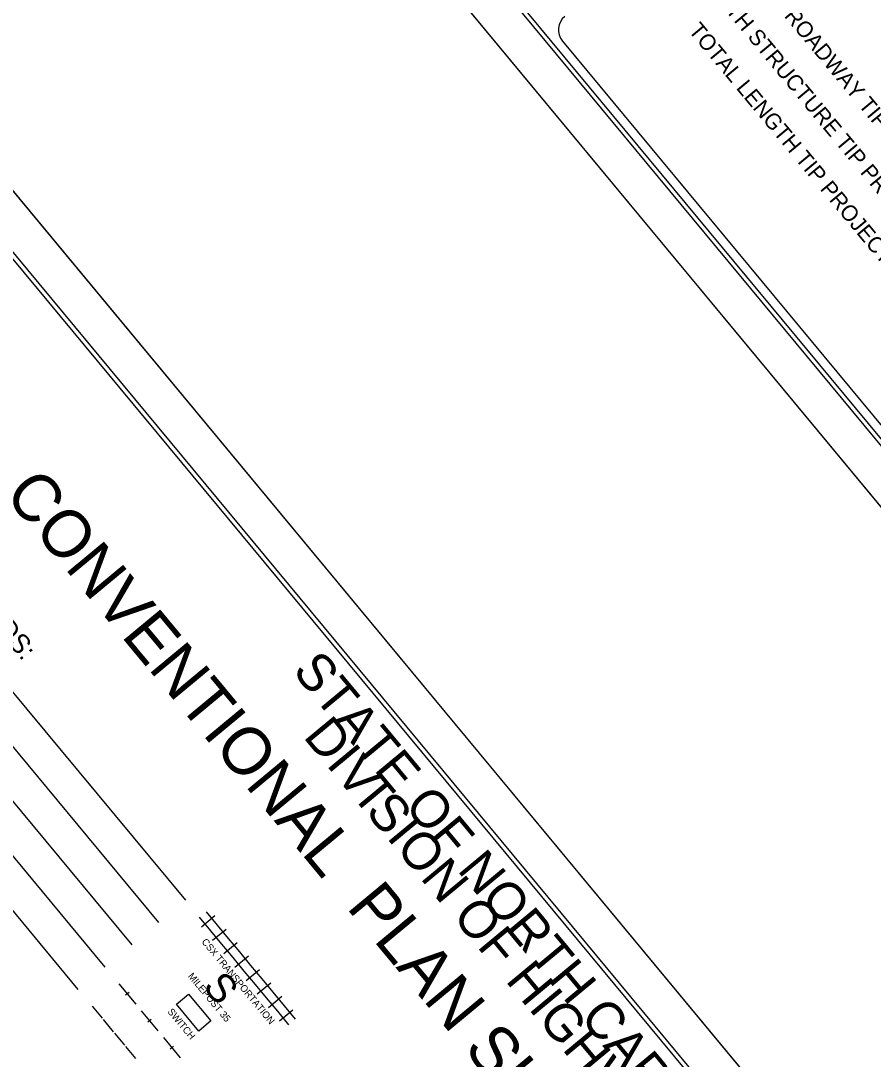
# Model space of a CAD drawing. Extents: x 2054826 to 2060231, y 685508 to 690809.
# Drawn here: x 2057466 to 2058198, y 687750 to 688643 of the extents above; entities that cross this region are included whole.
import ezdxf

# ---------------------------------------------------------------- set-up
doc = ezdxf.new("R2010")
doc.units = 0
for name, color, linetype in [('Old_Level_11', 7, 'Continuous'), ('Sheet Cutting Line CELL', 7, 'Continuous'), ('Sheet Plot Border Inside CELL', 7, 'Continuous'), ('Sheet Plot Border Outside CELL', 7, 'Continuous'), ('Sheet Symbology CELL', 7, 'Continuous'), ('Sheet Title CELL', 7, 'Continuous')]:
    doc.layers.add(name, color=color, linetype=linetype)

msp = doc.modelspace()

# ---------------------------------------------------------------- linework, layer by layer
at = {"layer": 'Sheet Cutting Line CELL'}
for p, q in [((2057348.74, 689256.87), (2058961.15, 687312.44)), ((2058650.7, 687059.77), (2057038.28, 689004.2))]:
    msp.add_line(p, q, dxfattribs=at)
at = {"layer": 'Sheet Plot Border Inside CELL'}
for points in [[(2057387.09, 689263.34), (2058982.75, 687339.12), (2060201.02, 688349.37), (2058605.36, 690273.59)], [(2055806.54, 687957.44), (2057402.2, 686033.22), (2058620.47, 687043.47), (2057024.81, 688967.69)]]:
    msp.add_lwpolyline(points, close=True, dxfattribs=at)
at = {"layer": 'Sheet Plot Border Outside CELL'}
for points in [[(2060231.25, 688365.67), (2058618.84, 690310.09), (2057348.74, 689256.87), (2058961.15, 687312.44)], [(2055768.17, 687950.96), (2057380.59, 686006.53), (2058650.7, 687059.77), (2057038.28, 689004.2)]]:
    msp.add_lwpolyline(points, close=True, dxfattribs=at)
at = {"layer": 'Sheet Symbology CELL'}
for p, q in [((2057561.4, 687848.66), (2057355.62, 688096.81)), ((2057607.59, 687886.96), (2057455.91, 688069.87)), ((2057584.49, 687867.81), (2057441.3, 688040.49)), ((2057538.31, 687829.51), (2057379.21, 688021.37)), ((2057515.21, 687810.36), (2057356.12, 688002.22)), ((2057515.21, 687810.36), (2057356.12, 688002.22)), ((2057624.95, 687877.21), (2057634.53, 687865.67)), ((2057619.18, 687872.43), (2057628.75, 687860.88)), ((2057621.08, 687864.26), (2057632.63, 687873.83)), ((2057634.53, 687865.67), (2057644.1, 687854.12)), ((2057628.75, 687860.88), (2057638.33, 687849.33)), ((2057630.65, 687852.71), (2057642.2, 687862.29)), ((2057638.33, 687849.33), (2057647.9, 687837.79)), ((2057640.23, 687841.17), (2057651.78, 687850.74)), ((2057644.1, 687854.12), (2057653.68, 687842.57)), ((2057649.8, 687829.62), (2057661.35, 687839.19)), ((2057653.68, 687842.57), (2057663.25, 687831.03)), ((2057647.9, 687837.79), (2057657.48, 687826.24)), ((2057663.25, 687831.03), (2057672.83, 687819.48)), ((2057657.48, 687826.24), (2057667.05, 687814.69)), ((2057659.38, 687818.07), (2057670.93, 687827.65)), ((2057550.17, 687815.2), (2057564.54, 687797.88)), ((2057667.05, 687814.69), (2057676.63, 687803.15)), ((2057668.95, 687806.53), (2057680.5, 687816.1)), ((2057672.83, 687819.48), (2057682.4, 687807.93)), ((2057558.8, 687807.74), (2057555.91, 687805.35)), ((2057676.63, 687803.15), (2057686.2, 687791.6)), ((2057678.53, 687794.98), (2057690.08, 687804.55)), ((2057682.4, 687807.93), (2057691.98, 687796.39)), ((2057527.08, 687796.05), (2057535.7, 687785.66)), ((2057691.98, 687796.39), (2057701.55, 687784.84)), ((2057569.32, 687792.11), (2057583.69, 687774.79)), ((2057686.2, 687791.6), (2057695.78, 687780.05)), ((2057688.1, 687783.43), (2057699.65, 687793.01)), ((2057536.66, 687784.51), (2057545.27, 687774.12)), ((2057577.95, 687784.65), (2057575.06, 687782.25)), ((2057546.23, 687772.96), (2057554.85, 687762.57)), ((2057588.47, 687769.02), (2057602.84, 687751.7)), ((2057555.81, 687761.41), (2057564.42, 687751.02)), ((2057597.1, 687761.55), (2057594.21, 687759.16))]:
    msp.add_line(p, q, dxfattribs=at)
for points in [[(2058605.56, 687055.46), (2057169.32, 688787.43), (2055958.11, 687783.04), (2057394.35, 686051.07)], [(2057610.03, 687806.38), (2057629.18, 687783.29), (2057618.67, 687774.57), (2057599.52, 687797.67)]]:
    msp.add_lwpolyline(points, close=True, dxfattribs=at)
at = {"layer": 'Sheet Title CELL'}
for points in [[(2057547.07, 689076.42), (2058964.15, 687367.54)], [(2057931.05, 688625.12), (2058294.89, 688186.36)]]:
    msp.add_lwpolyline(points, dxfattribs=at)
msp.add_arc((2057942.66, 688634.75), 15, 129.66721, 219.66721, dxfattribs=at)

# ---------------------------------------------------------------- texts
at = {"layer": 'Old_Level_11'}
for s, p in [('LENGTH ROADWAY TIP PROJECT B-4659 = ', (2058070.32, 688707.4)), ('LENGTH STRUCTURE TIP PROJECT B-4659 = ', (2058038.83, 688689.47)), ('TOTAL LENGTH TIP PROJECT B-4659 = ', (2058038.76, 688633.85))]:
    msp.add_text(s, height=13.672, rotation=309.74237, dxfattribs=at).set_placement(p)
at = {"layer": 'Sheet Symbology CELL'}
for s, height, p in [('CONVENTIONAL  PLAN SHEET SYMBOLS', 40.8005, (2057450.73, 688235.51)), ('RAILROADS:', 16.5, (2057382.33, 688194.91)), ('STATE OF NORTH CAROLINA', 32.1285, (2057698.41, 688083.69)), ('DIVISION OF HIGHWAYS', 32.1285, (2057707.73, 688027.41)), ('CSX TRANSPORTATION', 6, (2057620.74, 687851.19)), ('MILEPOST 35', 6, (2057609.04, 687821.64)), ('S', 24.75, (2057621.43, 687812.4)), ('SWITCH', 6, (2057591.49, 687791.11))]:
    msp.add_text(s, height=height, rotation=309.66721, dxfattribs=at).set_placement(p)

doc.saveas('drawing.dxf')
